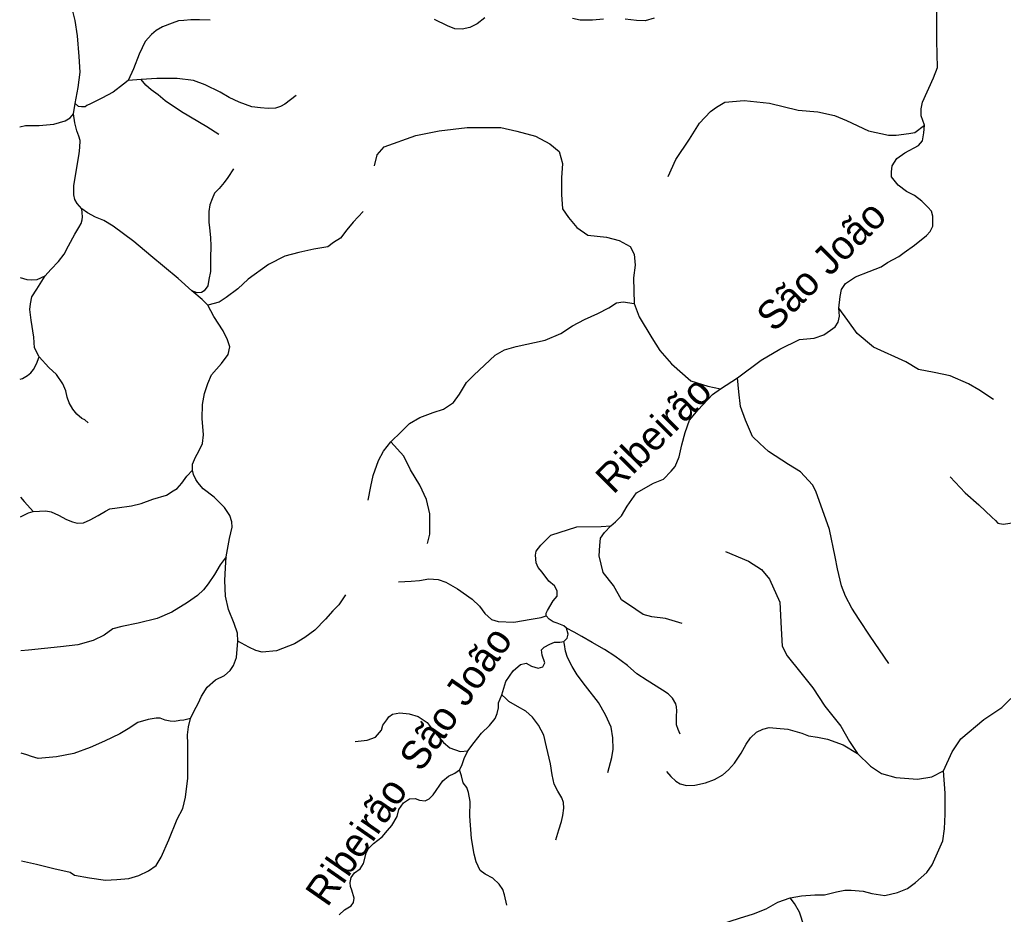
# Model space of a CAD drawing. Extents: x 436.3 to 500.4, y 8231 to 8286.4.
# Drawn here: x 446.4 to 453.25, y 8268.09 to 8274.32 of the extents above; entities that cross this region are included whole.
import ezdxf
from ezdxf.enums import TextEntityAlignment as Align

# ---------------------------------------------------------------- set-up
doc = ezdxf.new("R2010")
doc.units = 0
doc.header["$LTSCALE"] = 0.08
doc.linetypes.add('LONG_DASHED', pattern=[7.5, 6, -1.5])
doc.layers.add('61', color=7, linetype='Continuous')
doc.layers.add('9', color=7, linetype='LONG_DASHED', lineweight=25)

msp = doc.modelspace()

# ---------------------------------------------------------------- linework, layer by layer
at = {"layer": '9'}
msp.add_line((451.2828, 8271.7487), (451.4005, 8271.8246), dxfattribs=at)
for points in [[(452.7042, 8273.584), (452.6806, 8273.6503), (452.6806, 8273.6975), (452.69, 8273.7448), (452.7654, 8273.9147), (452.7937, 8273.9855), (452.789, 8274.1715), (452.789, 8274.3463), (452.7937, 8274.4551), (452.8078, 8274.5496), (452.8314, 8274.6157), (452.8973, 8274.7099), (452.9162, 8274.7712), (452.9256, 8274.8562), (452.9031, 8274.9515)], [(446.7879, 8273.7354), (446.8084, 8273.8467), (446.8211, 8273.9535), (446.8136, 8274.0629), (446.8035, 8274.2079), (446.7858, 8274.3147), (446.7629, 8274.4062), (446.7272, 8274.5021), (446.684, 8274.6114), (446.6544, 8274.7286)], [(447.7262, 8274.3164), (447.6523, 8274.3188), (447.5936, 8274.3189), (447.5436, 8274.3147), (447.5066, 8274.3104), (447.4631, 8274.2952), (447.3957, 8274.2694), (447.3501, 8274.2434), (447.3196, 8274.2152), (447.274, 8274.1675), (447.2327, 8274.0786), (447.1934, 8273.9765), (447.1565, 8273.8963)], [(449.6405, 8274.3333), (449.5863, 8274.291), (449.536, 8274.2641), (449.482, 8274.2526), (449.4317, 8274.2567), (449.3814, 8274.2761), (449.2892, 8274.3198)], [(450.468, 8274.3229), (450.3906, 8274.3155), (450.3056, 8274.3158), (450.2514, 8274.3275)], [(450.8198, 8274.3295), (450.758, 8274.3103), (450.6961, 8274.3145), (450.6188, 8274.3224)], [(447.1565, 8273.8963), (447.1232, 8273.8692), (447.0514, 8273.8152), (446.9732, 8273.7718), (446.9298, 8273.7524), (446.8928, 8273.7328), (446.8689, 8273.7221), (446.8559, 8273.7134), (446.8319, 8273.7134), (446.8102, 8273.7157), (446.7879, 8273.7354)], [(448.3274, 8273.7903), (448.2468, 8273.7318), (448.2164, 8273.7145), (448.1815, 8273.7038), (448.1315, 8273.6995), (448.0771, 8273.7062), (448.0184, 8273.713), (447.9293, 8273.7457), (447.8597, 8273.7763), (447.7967, 8273.8134), (447.6932, 8273.8664), (447.6106, 8273.8947), (447.4966, 8273.909), (447.3567, 8273.9093), (447.2472, 8273.9034), (447.1565, 8273.8963)], [(447.7887, 8273.5189), (447.7035, 8273.574), (447.527, 8273.6777), (447.4135, 8273.7529), (447.3657, 8273.7951), (447.3152, 8273.8318), (447.2787, 8273.8627), (447.2472, 8273.9034)], [(450.9186, 8273.2276), (450.9715, 8273.3451), (451.0657, 8273.4861), (451.1363, 8273.5976), (451.2128, 8273.6798), (451.2539, 8273.709), (451.3127, 8273.7441), (451.448, 8273.7554), (451.6245, 8273.737), (451.8244, 8273.689), (451.9598, 8273.6767), (452.0774, 8273.6527), (452.1597, 8273.617), (452.3125, 8273.5456), (452.4537, 8273.5156), (452.5066, 8273.5154), (452.5948, 8273.5268), (452.636, 8273.5325), (452.7042, 8273.584)], [(446.8335, 8273.0024), (446.8004, 8273.0381), (446.7851, 8273.0662), (446.7774, 8273.0993), (446.7775, 8273.1629), (446.7979, 8273.2901), (446.8157, 8273.3842), (446.8184, 8273.43), (446.8209, 8273.4784), (446.8133, 8273.5089), (446.798, 8273.5446), (446.7854, 8273.6006), (446.7752, 8273.6642), (446.7879, 8273.7354)], [(446.4002, 8273.574), (446.4414, 8273.5817), (446.5349, 8273.5816), (446.6381, 8273.5912), (446.7167, 8273.6157), (446.7511, 8273.6352), (446.7752, 8273.6642)], [(448.8727, 8273.3019), (448.8911, 8273.3782), (448.9392, 8273.4336), (449.1609, 8273.5133), (449.3235, 8273.5459), (449.5164, 8273.5683), (449.7517, 8273.5674), (449.8635, 8273.5435), (449.993, 8273.5077), (450.093, 8273.4542), (450.1577, 8273.401), (450.1812, 8273.3186), (450.1753, 8273.2185), (450.1753, 8273.1009), (450.1812, 8273.0007), (450.2224, 8272.9417), (450.2812, 8272.8708), (450.3577, 8272.8174), (450.4872, 8272.8051), (450.5755, 8272.7811), (450.652, 8272.7395), (450.6813, 8272.6863), (450.6873, 8272.6097), (450.6756, 8272.5215), (450.6812, 8272.3415)], [(452.1056, 8272.3088), (452.1149, 8272.3922), (452.1244, 8272.4393), (452.1526, 8272.4818), (452.2234, 8272.5287), (452.3177, 8272.5661), (452.4026, 8272.5988), (452.445, 8272.627), (452.5252, 8272.6691), (452.5629, 8272.6974), (452.6336, 8272.749), (452.7185, 8272.8149), (452.742, 8272.8431), (452.7609, 8272.8809), (452.7609, 8272.9518), (452.7514, 8272.9849), (452.7278, 8273.0134), (452.6854, 8273.0561), (452.6335, 8273.0942), (452.5769, 8273.1228), (452.5203, 8273.1655), (452.4732, 8273.2257), (452.4732, 8273.2588), (452.4779, 8273.3013), (452.5109, 8273.3531), (452.5675, 8273.3908), (452.6618, 8273.4423), (452.6901, 8273.4754), (452.6994, 8273.532), (452.7042, 8273.584)], [(447.8889, 8273.2796), (447.8495, 8273.2212), (447.8238, 8273.1853), (447.7904, 8273.1442), (447.757, 8273.1109), (447.7414, 8273.0724), (447.726, 8273.0287), (447.7183, 8272.9824), (447.7183, 8272.9079), (447.7234, 8272.8693), (447.7285, 8272.8024), (447.731, 8272.7406), (447.7285, 8272.6609), (447.7285, 8272.5657), (447.7181, 8272.5091), (447.7104, 8272.4653), (447.6847, 8272.4295), (447.6666, 8272.4193), (447.6358, 8272.4167), (447.6005, 8272.4312)], [(446.5782, 8272.5359), (446.6165, 8272.5797), (446.671, 8272.636), (446.7098, 8272.6852), (446.7397, 8272.745), (446.7855, 8272.8254), (446.8119, 8272.8711), (446.8278, 8272.8992), (446.8366, 8272.9256), (446.8384, 8272.9467), (446.8335, 8273.0024)], [(447.6005, 8272.4312), (447.5037, 8272.5154), (447.3129, 8272.6738), (447.1958, 8272.7734), (447.0508, 8272.8807), (446.986, 8272.9207), (446.9276, 8272.9437), (446.8716, 8272.9744), (446.8335, 8273.0024)], [(448.7935, 8272.9825), (448.723, 8272.908), (448.679, 8272.8553), (448.635, 8272.7983), (448.5865, 8272.7677), (448.5469, 8272.737), (448.4501, 8272.7199), (448.3444, 8272.6982), (448.2476, 8272.6722), (448.1329, 8272.6152), (447.9926, 8272.5115), (447.9203, 8272.4445), (447.8386, 8272.3831), (447.7893, 8272.352), (447.71, 8272.3307)], [(446.4026, 8272.5226), (446.4492, 8272.5096), (446.4837, 8272.5068), (446.5224, 8272.5092), (446.5782, 8272.5359)], [(446.5369, 8271.9705), (446.5045, 8272.0342), (446.4995, 8272.108), (446.4799, 8272.2261), (446.47, 8272.3), (446.4749, 8272.3393), (446.4848, 8272.3884), (446.5192, 8272.4424), (446.5782, 8272.5359)], [(447.71, 8272.3307), (447.6718, 8272.3699), (447.6005, 8272.4312)], [(447.6037, 8271.1811), (447.6037, 8271.2244), (447.624, 8271.2728), (447.6494, 8271.3136), (447.6749, 8271.367), (447.68, 8271.4283), (447.6722, 8271.5405), (447.6747, 8271.64), (447.6875, 8271.7156), (447.7104, 8271.7844), (447.7359, 8271.8455), (447.8072, 8271.9244), (447.8529, 8271.988), (447.8631, 8272.0415), (447.8478, 8272.0899), (447.8173, 8272.1511), (447.7536, 8272.2507), (447.71, 8272.3307)], [(448.9869, 8271.3787), (449.0575, 8271.449), (449.1163, 8271.5076), (449.1869, 8271.5485), (449.281, 8271.5833), (449.3516, 8271.6064), (449.4222, 8271.6532), (449.4633, 8271.7119), (449.5132, 8271.7911), (449.565, 8271.8432), (449.7119, 8271.982), (449.7785, 8272.0202), (449.8587, 8272.0433), (450.061, 8272.0873), (450.1696, 8272.1336), (450.2522, 8272.1868), (450.334, 8272.2313), (450.4281, 8272.2721), (450.5046, 8272.313), (450.5576, 8272.348), (450.6047, 8272.3536), (450.6812, 8272.3415)], [(450.6812, 8272.3415), (450.7168, 8272.2504), (450.8051, 8272.1026), (450.8591, 8272.0159), (450.9414, 8271.9212), (451.0768, 8271.8028), (451.1945, 8271.7668), (451.2828, 8271.7487)], [(451.4005, 8271.8246), (451.5651, 8271.9476), (451.6945, 8272.0235), (451.832, 8272.0911), (451.9358, 8272.1), (452.0019, 8272.1233), (452.049, 8272.1562), (452.082, 8272.1796), (452.1009, 8272.2127), (452.1103, 8272.2551), (452.1056, 8272.3088)], [(453.1844, 8271.674), (453.0816, 8271.741), (453.0092, 8271.7837), (452.8823, 8271.8387), (452.7719, 8271.8628), (452.6615, 8271.8823), (452.5742, 8271.9369), (452.3489, 8272.0387), (452.2351, 8272.1341), (452.1693, 8272.2233), (452.1056, 8272.3088)], [(446.4043, 8271.8153), (446.4208, 8271.821), (446.4542, 8271.8404), (446.4789, 8271.8597), (446.4965, 8271.8826), (446.5176, 8271.923), (446.5369, 8271.9705)], [(446.878, 8271.5117), (446.8534, 8271.5314), (446.8338, 8271.5414), (446.7993, 8271.5709), (446.7698, 8271.6055), (446.7453, 8271.6498), (446.7305, 8271.6892), (446.7207, 8271.7335), (446.7011, 8271.7829), (446.6568, 8271.8469), (446.6027, 8271.8963), (446.5369, 8271.9705)], [(452.4539, 8269.835), (452.3257, 8270.0249), (452.2477, 8270.1423), (452.1975, 8270.2205), (452.1529, 8270.3043), (452.125, 8270.3768), (452.0971, 8270.4941), (452.0803, 8270.5778), (452.0412, 8270.7675), (451.9464, 8271.0356), (451.924, 8271.0804), (451.8405, 8271.17), (451.7569, 8271.2206), (451.6176, 8271.3106), (451.5563, 8271.3666), (451.5062, 8271.417), (451.456, 8271.5289), (451.4225, 8271.6239), (451.4111, 8271.7263), (451.4005, 8271.8246)], [(450.518, 8270.7941), (450.5511, 8270.8222), (450.5935, 8270.8645), (450.6312, 8270.9304), (450.6972, 8271.0245), (450.8151, 8271.09), (450.8859, 8271.118), (450.9378, 8271.1744), (450.9661, 8271.2073), (450.9944, 8271.2733), (451.0132, 8271.3583), (451.0368, 8271.4432), (451.0666, 8271.5307), (451.1278, 8271.6012), (451.2269, 8271.7093), (451.2828, 8271.7487)], [(448.8284, 8270.9732), (448.8459, 8271.0674), (448.8635, 8271.1439), (448.8988, 8271.2496), (448.934, 8271.3142), (448.9869, 8271.3787)], [(449.2404, 8270.6707), (449.2581, 8270.7355), (449.2579, 8270.8768), (449.2343, 8270.977), (449.1872, 8271.0773), (449.1223, 8271.1838), (449.0752, 8271.2781), (448.9869, 8271.3787)], [(446.4942, 8270.8941), (446.5383, 8270.8968), (446.5825, 8270.8994), (446.6185, 8270.8911), (446.671, 8270.8688), (446.7263, 8270.8382), (446.7678, 8270.8214), (446.801, 8270.813), (446.8452, 8270.8157), (446.8922, 8270.8349), (446.9474, 8270.8652), (446.9972, 8270.8956), (447.0276, 8270.9121), (447.0801, 8270.9202), (447.1795, 8270.9337), (447.2459, 8270.9501), (447.3288, 8270.9804), (447.4228, 8271.0077), (447.4698, 8271.0381), (447.4975, 8271.0545), (447.5307, 8271.0904), (447.5637, 8271.1402), (447.6037, 8271.1811)], [(447.8387, 8270.5779), (447.8615, 8270.7053), (447.8796, 8270.7835), (447.877, 8270.8218), (447.8642, 8270.8652), (447.826, 8270.9215), (447.7546, 8270.9932), (447.6781, 8271.0522), (447.642, 8271.0967), (447.6267, 8271.1173), (447.6113, 8271.1504), (447.6037, 8271.1811)], [(452.883, 8271.134), (452.9857, 8271.0247), (453.0824, 8270.9397), (453.173, 8270.8547), (453.1972, 8270.8304), (453.2154, 8270.8122), (453.2516, 8270.806), (453.33, 8270.8179)], [(446.4062, 8270.9943), (446.4306, 8270.9635), (446.4555, 8270.9385), (446.4942, 8270.8941)], [(446.4065, 8270.8561), (446.461, 8270.8832), (446.4942, 8270.8941)], [(450.0673, 8270.1661), (450.0689, 8270.1866), (450.0765, 8270.2032), (450.116, 8270.2713), (450.1443, 8270.3043), (450.1443, 8270.342), (450.1253, 8270.3751), (450.0876, 8270.4084), (450.0403, 8270.4701), (450.012, 8270.5033), (449.9978, 8270.5364), (449.9931, 8270.5884), (449.9977, 8270.6167), (450.0308, 8270.659), (450.1015, 8270.7295), (450.2821, 8270.7859), (450.452, 8270.7898), (450.518, 8270.7941)], [(451.0162, 8270.114), (450.8992, 8270.1482), (450.8044, 8270.1598), (450.7431, 8270.1768), (450.693, 8270.2106), (450.5927, 8270.278), (450.5369, 8270.3786), (450.4644, 8270.4682), (450.4365, 8270.5855), (450.442, 8270.6579), (450.4475, 8270.7081), (450.4753, 8270.747), (450.518, 8270.7941)], [(451.3167, 8270.6142), (451.4783, 8270.5465), (451.5674, 8270.4903), (451.6231, 8270.423), (451.6956, 8270.2611), (451.7044, 8270.0781), (451.7126, 8269.9545), (451.7461, 8269.8875), (451.8408, 8269.77), (451.9251, 8269.6665), (452.0087, 8269.5381), (452.1202, 8269.3984), (452.1815, 8269.2924), (452.2372, 8269.2087)], [(447.8387, 8270.5779), (447.7973, 8270.5212), (447.757, 8270.4551), (447.713, 8270.3891), (447.6799, 8270.3488), (447.6395, 8270.3084), (447.5698, 8270.2609), (447.4597, 8270.1915), (447.3569, 8270.1476), (447.2247, 8270.115), (447.1108, 8270.0934), (447.0484, 8270.0752), (446.9897, 8270.0313), (446.9127, 8269.9948), (446.8062, 8269.9658), (446.685, 8269.9514), (446.4621, 8269.9267), (446.4087, 8269.9222)], [(447.9203, 8269.9906), (447.9181, 8270.0468), (447.8951, 8270.1133), (447.8543, 8270.2103), (447.8338, 8270.3048), (447.8286, 8270.412), (447.8336, 8270.5013), (447.8387, 8270.5779)], [(449.0395, 8270.4031), (449.1277, 8270.4085), (449.1865, 8270.414), (449.2512, 8270.4255), (449.3159, 8270.4193), (449.3689, 8270.4013), (449.4513, 8270.3538), (449.5514, 8270.2825), (449.6044, 8270.2351), (449.6397, 8270.182), (449.6868, 8270.1405), (449.7339, 8270.1285), (449.8423, 8270.1218), (449.9634, 8270.1448), (450.034, 8270.1562), (450.0673, 8270.1661)], [(448.6692, 8270.312), (448.6243, 8270.2431), (448.5829, 8270.2019), (448.5312, 8270.1433), (448.4553, 8270.0676), (448.3863, 8270.0161), (448.3139, 8269.9715), (448.1896, 8269.9238), (448.0896, 8269.9138), (448.0446, 8269.9244), (447.9963, 8269.9488), (447.9203, 8269.9906)], [(450.2105, 8270.0819), (450.1917, 8270.0962), (450.1445, 8270.1153), (450.1161, 8270.1249), (450.0878, 8270.144), (450.0673, 8270.1661)], [(450.1918, 8269.9876), (450.2153, 8270.0111), (450.22, 8270.0393), (450.2105, 8270.0819)], [(451.0007, 8269.3436), (450.9863, 8269.376), (450.9756, 8269.4082), (450.9756, 8269.469), (450.9791, 8269.5047), (450.9755, 8269.5333), (450.9719, 8269.5548), (450.9468, 8269.5944), (450.9182, 8269.6231), (450.8789, 8269.6484), (450.7715, 8269.717), (450.6999, 8269.7639), (450.6355, 8269.8215), (450.546, 8269.8864), (450.4743, 8269.9334), (450.3885, 8269.9803), (450.3169, 8270.0237), (450.2632, 8270.0526), (450.2105, 8270.0819)], [(447.5897, 8269.4517), (447.6152, 8269.5053), (447.6432, 8269.5561), (447.668, 8269.607), (447.7065, 8269.6707), (447.7635, 8269.7208), (447.827, 8269.7507), (447.8677, 8269.7862), (447.8905, 8269.8218), (447.9109, 8269.8778), (447.9203, 8269.9906)], [(449.7579, 8269.6172), (449.7864, 8269.71), (449.8379, 8269.7848), (449.8898, 8269.8269), (449.9275, 8269.8361), (449.9653, 8269.8171), (450.0125, 8269.8026), (450.0455, 8269.8119), (450.0596, 8269.8401), (450.0407, 8269.8922), (450.036, 8269.9299), (450.0548, 8269.9488), (450.0926, 8269.9692), (450.1257, 8269.9833), (450.1634, 8269.9831), (450.1918, 8269.9876)], [(450.4966, 8269.0766), (450.5251, 8269.1802), (450.5357, 8269.2374), (450.5321, 8269.316), (450.5214, 8269.3913), (450.4819, 8269.4774), (450.4318, 8269.5635), (450.3419, 8269.6803), (450.2845, 8269.7558), (450.2487, 8269.8132), (450.2165, 8269.8778), (450.2021, 8269.921), (450.1949, 8269.9674), (450.1918, 8269.9876)], [(449.5223, 8269.226), (449.5669, 8269.2839), (449.6183, 8269.3507), (449.6742, 8269.4041), (449.7122, 8269.4509), (449.7255, 8269.4866), (449.7366, 8269.5268), (449.7366, 8269.5604), (449.7579, 8269.6172)], [(450.1344, 8268.6057), (450.1558, 8268.677), (450.1737, 8268.7341), (450.1843, 8268.7769), (450.1914, 8268.827), (450.1879, 8268.8663), (450.177, 8268.8985), (450.1484, 8268.9452), (450.1234, 8268.9954), (450.109, 8269.0598), (450.0982, 8269.135), (450.0694, 8269.254), (450.0514, 8269.3365), (450.0156, 8269.4047), (449.9726, 8269.4622), (449.9261, 8269.5017), (449.8688, 8269.5342), (449.808, 8269.5704), (449.7865, 8269.592), (449.7579, 8269.6172)], [(452.8352, 8269.0883), (452.8966, 8269.2199), (452.9575, 8269.3112), (453.1168, 8269.4453), (453.2412, 8269.5283), (453.3049, 8269.59)], [(447.5897, 8269.4517), (447.5437, 8269.4402), (447.5158, 8269.4369), (447.4793, 8269.4318), (447.4497, 8269.4337), (447.4126, 8269.4405), (447.378, 8269.4545), (447.3504, 8269.4546), (447.2951, 8269.4445), (447.2226, 8269.424), (447.1571, 8269.3794), (447.0984, 8269.345), (446.9914, 8269.2936), (446.8913, 8269.2489), (446.7774, 8269.2079), (446.6566, 8269.1841), (446.5288, 8269.1742), (446.4816, 8269.1879), (446.4491, 8269.1987), (446.4104, 8269.2097)], [(446.4122, 8268.4613), (446.5175, 8268.4365), (446.6373, 8268.408), (446.7519, 8268.3821), (446.7825, 8268.3616), (446.8869, 8268.3409), (446.9991, 8268.3251), (447.078, 8268.3299), (447.1595, 8268.3372), (447.2309, 8268.3573), (447.2971, 8268.3902), (447.3506, 8268.4282), (447.3861, 8268.4867), (447.4395, 8268.6062), (447.498, 8268.7513), (447.5362, 8268.8251), (447.5565, 8268.904), (447.5716, 8269.0365), (447.5721, 8269.2758), (447.5695, 8269.3371), (447.5771, 8269.3931), (447.5897, 8269.4517)], [(448.7366, 8269.2926), (448.8203, 8269.3005), (448.8788, 8269.3211), (448.9206, 8269.3712), (448.929, 8269.4046), (448.9582, 8269.4422), (448.9708, 8269.4631), (448.9967, 8269.4817), (449.0479, 8269.492), (449.113, 8269.4832), (449.1758, 8269.4661), (449.2389, 8269.4234), (449.2806, 8269.3692), (449.3518, 8269.2851), (449.3979, 8269.2472), (449.4691, 8269.2217), (449.5223, 8269.226)], [(450.9069, 8269.0829), (450.9373, 8269.0468), (450.9704, 8269.0163), (451.0009, 8268.9969), (451.045, 8268.9855), (451.103, 8268.988), (451.1775, 8269.0042), (451.241, 8269.0259), (451.2989, 8269.0588), (451.3375, 8269.0945), (451.3789, 8269.1412), (451.4258, 8269.2099), (451.4617, 8269.2733), (451.492, 8269.3173), (451.5333, 8269.3558), (451.5774, 8269.3776), (451.6216, 8269.3885), (451.6714, 8269.3855), (451.7514, 8269.3769), (451.848, 8269.3489), (451.895, 8269.332), (451.9584, 8269.3208), (452.0274, 8269.3067), (452.1379, 8269.2676), (452.2372, 8269.2087)], [(449.4643, 8269.0944), (449.48, 8269.1234), (449.4955, 8269.1725), (449.5223, 8269.226)], [(452.2372, 8269.2087), (452.3264, 8269.1194), (452.4044, 8269.069), (452.5046, 8269.0409), (452.6549, 8269.0294), (452.7551, 8269.0457), (452.8352, 8269.0883)], [(448.6249, 8268.0848), (448.6635, 8268.1194), (448.7099, 8268.1462), (448.7263, 8268.17), (448.7303, 8268.2011), (448.7131, 8268.2558), (448.7043, 8268.2819), (448.702, 8268.3085), (448.7097, 8268.3433), (448.7328, 8268.376), (448.7725, 8268.4046), (448.7956, 8268.441), (448.8137, 8268.5127), (448.8289, 8268.5449), (448.8649, 8268.5804), (448.9259, 8268.6281), (448.9619, 8268.6723), (448.9924, 8268.7061), (449.0303, 8268.7686), (449.0414, 8268.8176), (449.0749, 8268.8645), (449.1151, 8268.8932), (449.1554, 8268.8953), (449.1866, 8268.8839), (449.2247, 8268.8793), (449.2537, 8268.8925), (449.2805, 8268.9192), (449.3481, 8269.0183), (449.3883, 8269.0501), (449.4308, 8269.07), (449.4643, 8269.0944)], [(449.7936, 8268.1506), (449.7783, 8268.2239), (449.766, 8268.2605), (449.7416, 8268.2973), (449.6957, 8268.3403), (449.6437, 8268.368), (449.607, 8268.3927), (449.5795, 8268.4538), (449.5673, 8268.5058), (449.5488, 8268.6158), (449.5365, 8268.7715), (449.5388, 8268.8731), (449.5265, 8268.9373), (449.5143, 8268.9709), (449.4898, 8269.0046), (449.4775, 8269.0535), (449.4643, 8269.0944)], [(451.7678, 8268.2035), (451.846, 8268.2162), (451.9405, 8268.2241), (452.0063, 8268.2239), (452.0902, 8268.2448), (452.1477, 8268.257), (452.1929, 8268.2568), (452.2751, 8268.2484), (452.3368, 8268.2319), (452.4282, 8268.2199), (452.5144, 8268.2402), (452.5841, 8268.2687), (452.6417, 8268.3096), (452.7197, 8268.3792), (452.7566, 8268.4324), (452.8304, 8268.6003), (452.8427, 8268.6823), (452.8468, 8268.7849), (452.8467, 8268.9326), (452.8352, 8269.0883)], [(450.5433, 8267.4195), (450.5744, 8267.4943), (450.6114, 8267.5679), (450.6566, 8267.6251), (450.71, 8267.6904), (450.7757, 8267.7516), (450.8784, 8267.8167), (451.0057, 8267.894), (451.1763, 8267.9853), (451.4146, 8268.0621), (451.5132, 8268.0904), (451.5995, 8268.127), (451.6817, 8268.1717), (451.7678, 8268.2035)], [(451.6419, 8267.4727), (451.7286, 8267.5036), (451.8024, 8267.5416), (451.8599, 8267.5769), (451.8818, 8267.6068), (451.8982, 8267.634), (451.9091, 8267.7022), (451.9063, 8267.8248), (451.8925, 8267.9122), (451.8652, 8268.0023), (451.8323, 8268.1034), (451.7967, 8268.1637), (451.7678, 8268.2035)]]:
    msp.add_lwpolyline(points, dxfattribs=at)

# ---------------------------------------------------------------- texts
at = {"layer": '61'}
for s, rotation, p in [('Ribeirão        São João', 45.197, (451.4939, 8271.9728)), ('Ribeirão  São João', 55.197, (449.1922, 8269.0655))]:
    msp.add_text(s, height=0.2, rotation=rotation, dxfattribs=at).set_placement(p, align=Align.CENTER)

doc.saveas('drawing.dxf')
